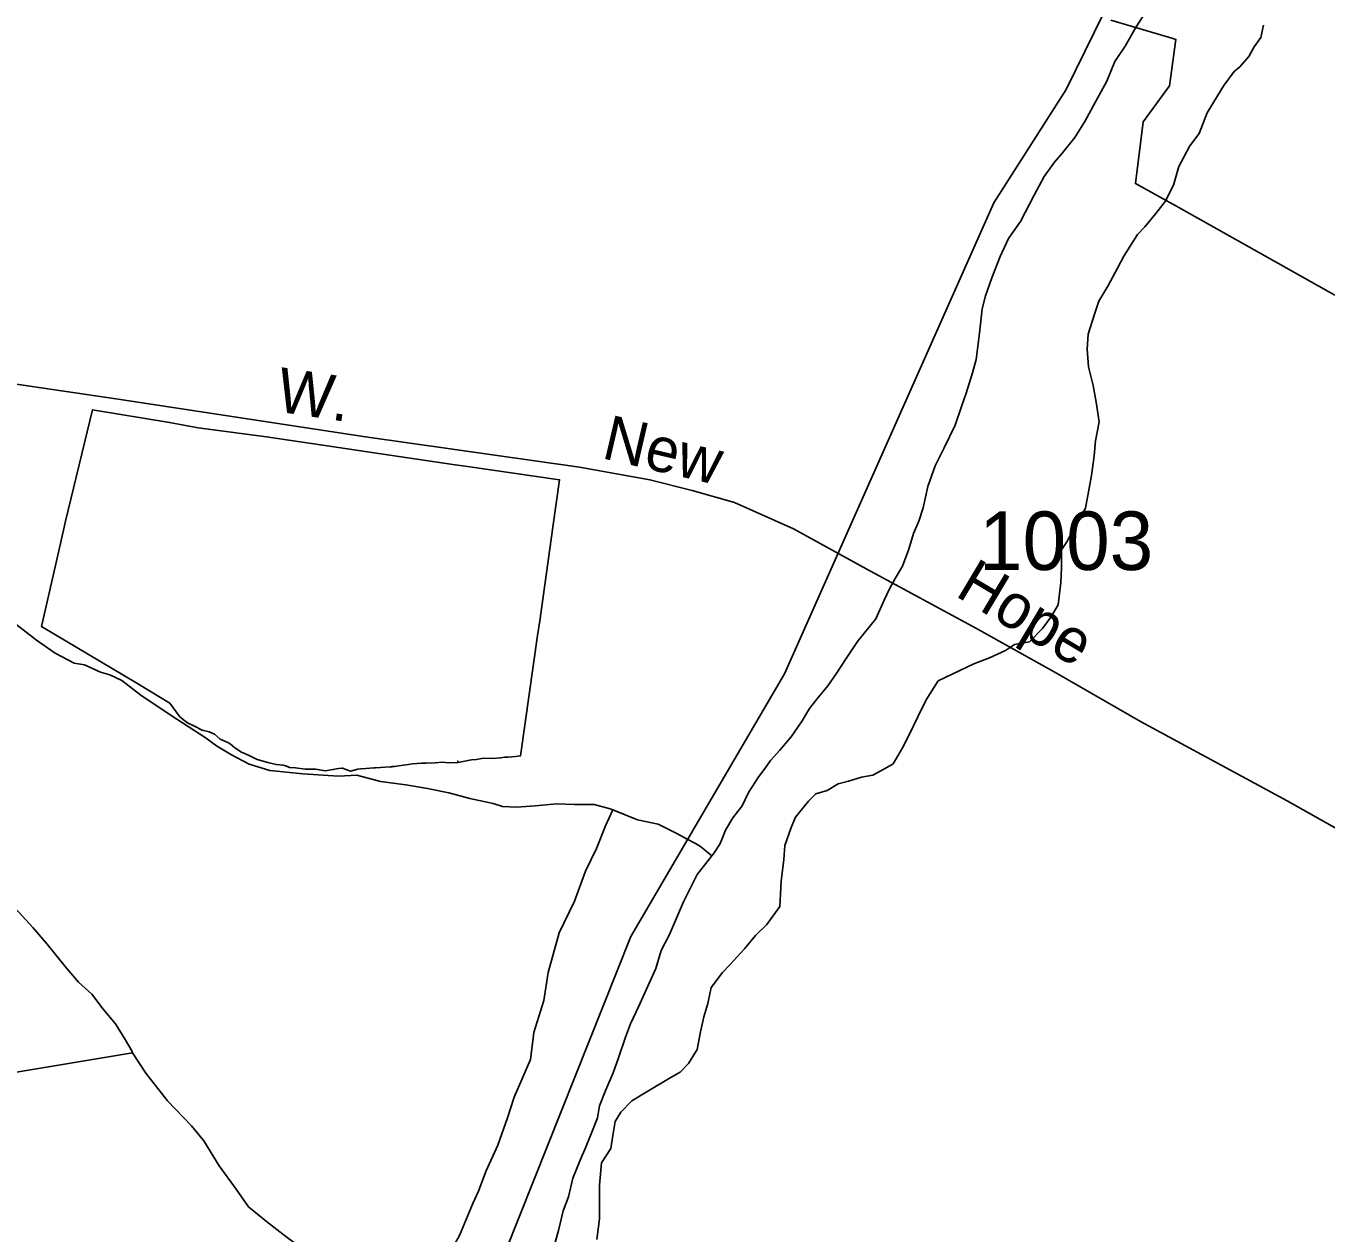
# Model space of a CAD drawing. Extents: x 2260773 to 2342389, y 552869 to 618546.
# Drawn here: x 2309662 to 2312438, y 605993 to 608571 of the extents above; entities that cross this region are included whole.
import ezdxf

# ---------------------------------------------------------------- set-up
doc = ezdxf.new("R2010")
doc.units = 0
for name, color, linetype in [('Exist Boundary Political City Limit New', 7, 'Continuous'), ('Exist Hydrographic Creek Single Shore', 7, 'Continuous'), ('Exist Hydrographic Misc Water Feature', 7, 'Continuous'), ('Exist Road Secondary Type 51 Attributed', 7, 'Continuous'), ('Exist Road Secondary Type 51 Label', 7, 'Continuous'), ('Exist Road Secondary Type 51 Number Label', 7, 'Continuous'), ('Map Preparation Boundary City Limit Buffer Line', 7, 'Continuous')]:
    doc.layers.add(name, color=color, linetype=linetype)

msp = doc.modelspace()

# ---------------------------------------------------------------- linework, layer by layer
at = {"layer": 'Exist Boundary Political City Limit New'}
for points in [[(2312456.5, 607995.6), (2312123.2, 608182.8), (2312030.8, 608234.4), (2312047.2, 608366.1), (2312103.8, 608442.9), (2312117.2, 608542.2), (2312108.8, 608544.8), (2311978.5, 608583.2)], [(2310419, 607657.1), (2310578, 607633.8), (2310583.5, 607633), (2310599.2, 607630.7), (2310801, 607601.7), (2310786.5, 607500), (2310758.5, 607299.9), (2310754, 607268.6), (2310718.5, 607016.7), (2310717.8, 607012.2), (2310707.2, 607010.8), (2310691, 607009.1), (2310683.5, 607008.8), (2310675.5, 607007.5), (2310657.8, 607006.5), (2310638.8, 607007.2), (2310623.5, 607004.1), (2310613.2, 607003), (2310605.5, 607002.2), (2310584.2, 606997.8), (2310583.5, 607001), (2310583.5, 606997.8), (2310563, 606996.6), (2310550.2, 606998.4), (2310535.2, 606997.2), (2310516, 606996.2), (2310505.8, 606995.9), (2310497.2, 606995.6), (2310486, 606994.6), (2310478.2, 606993.6), (2310457, 606990.5), (2310448.5, 606989.2), (2310445, 606988.9), (2310444.2, 606988.8), (2310443.2, 606988.7), (2310439.2, 606988.3), (2310418.8, 606986.7), (2310408.2, 606986.2), (2310404.2, 606986), (2310387.5, 606985), (2310376.2, 606983.9), (2310370, 606983.3), (2310354.5, 606978.8), (2310347, 606981.8), (2310337.2, 606985.8), (2310336.5, 606985.7), (2310335.8, 606985.6), (2310329.2, 606985.1), (2310317, 606982.4), (2310301, 606980.2), (2310279.5, 606983.4), (2310257.5, 606983.2), (2310237.2, 606986.2), (2310224.5, 606987.2), (2310216.2, 606990.3), (2310215.5, 606990.8), (2310210.5, 606991.7), (2310196, 606993.6), (2310177.8, 606997.6), (2310155.2, 607004.3), (2310138, 607012.4), (2310121.8, 607019.6), (2310107.8, 607028.8), (2310097.2, 607037.8), (2310092.8, 607040.2), (2310076, 607047.5), (2310063.8, 607058.2), (2310052.5, 607062.9), (2310037.5, 607066.9), (2310021, 607075.5), (2310006.5, 607082.1), (2310000.8, 607086.6), (2309990.2, 607095.1), (2309968.5, 607124.5), (2309898.5, 607166.9), (2309894.8, 607169.5), (2309720.8, 607272.5), (2309694.8, 607287.8), (2309731.5, 607449.9), (2309743, 607500), (2309746, 607512.8), (2309803.2, 607751), (2309968, 607723.9), (2310029, 607712.8), (2310175.2, 607693), (2310198.5, 607689.6), (2310295.2, 607675.3), (2310419, 607657.1)]]:
    msp.add_lwpolyline(points, dxfattribs=at)
at = {"layer": 'Exist Hydrographic Creek Single Shore'}
msp.add_lwpolyline([(2310686.2, 605955.4), (2310953.2, 606625.8), (2311281.1, 607187.1), (2311728.1, 608192.9), (2311883.1, 608435.5), (2312022.1, 608720)], dxfattribs=at)
at = {"layer": 'Exist Hydrographic Misc Water Feature'}
for points in [[(2312063.9, 608617.8), (2312032.6, 608569.4), (2312009, 608527.5), (2311987.1, 608495.1), (2311969.8, 608453), (2311945.8, 608408.8), (2311922.7, 608366.5), (2311901.3, 608332.4), (2311875.1, 608300.2), (2311857.7, 608279.7), (2311836.1, 608249.7), (2311814.6, 608209.2), (2311785.3, 608153.2), (2311759.6, 608116.9), (2311741.8, 608078.6), (2311724.4, 608032.6), (2311710.8, 607994.4), (2311703.1, 607966.4), (2311697.9, 607914.5), (2311690.3, 607858.4), (2311682.5, 607830), (2311669.2, 607786.2), (2311659.6, 607758), (2311646, 607717.9), (2311622.3, 607669.6), (2311602.8, 607631.6), (2311587.4, 607587.2), (2311577.6, 607541.3), (2311568.1, 607513.1), (2311556.6, 607486.8), (2311546.8, 607453), (2311533.1, 607417), (2311517.3, 607390.6), (2311505.4, 607368.4), (2311493.9, 607344.6), (2311476.5, 607304.2), (2311436.9, 607255.8), (2311413.1, 607219.7), (2311391.6, 607187.3), (2311373.9, 607161.1), (2311350.2, 607133), (2311334.6, 607112.7), (2311318.8, 607086.7), (2311295.2, 607052.5), (2311271.4, 607024.1), (2311251.5, 607001.9), (2311239.8, 606985.8), (2311226.3, 606967.6), (2311204.4, 606933.6), (2311190.8, 606905.2), (2311171.1, 606879.4), (2311155.4, 606853), (2311147.8, 606833), (2311143.5, 606823.1), (2311129.9, 606802.8), (2311125.8, 606798.6)], [(2310880.6, 605978.6), (2310886.3, 606022.8), (2310886.1, 606062.5), (2310885.9, 606094.6), (2310890.8, 606142.5), (2310910.7, 606172.8), (2310914.6, 606200.6), (2310920, 606231), (2310931.9, 606251.1), (2310955.4, 606275.1), (2310989.5, 606295.6), (2311037, 606324.1), (2311058.8, 606336.2), (2311076.6, 606354.6), (2311094.5, 606384.8), (2311102, 606422.6), (2311109.4, 606454.7), (2311117.4, 606482.7), (2311124.8, 606516.9), (2311148.6, 606549), (2311164.4, 606565.3), (2311196, 606599.8), (2311219.5, 606628), (2311243.3, 606651.9), (2311271, 606690.4), (2311274.1, 606744.2), (2311279.6, 606790.4), (2311281.7, 606820.6), (2311295.2, 606858.7), (2311304.8, 606880.7), (2311332.7, 606915.1), (2311348.5, 606930.9), (2311372.5, 606937.5), (2311396.1, 606951.8), (2311418, 606957.8), (2311445.7, 606966.2), (2311469.7, 606970.3), (2311499.6, 606986.8), (2311513.4, 606994.9), (2311533.1, 607028.9), (2311546.8, 607055.2), (2311566.3, 607095.2), (2311584.1, 607131.5), (2311609.6, 607171.9), (2311639.1, 607186.1), (2311685.4, 607208.7), (2311718.8, 607221.1), (2311753.1, 607237), (2311772.6, 607249.5), (2311804.6, 607255.6), (2311832.2, 607283.9), (2311849.9, 607308.4), (2311865.7, 607334.4), (2311871.2, 607382.3), (2311872.6, 607414.5), (2311872.6, 607452.2), (2311884.3, 607468.7), (2311901.7, 607502.6), (2311923.9, 607541), (2311936.8, 607610.8), (2311942.6, 607653), (2311945.6, 607685), (2311953.6, 607725.1), (2311947.1, 607767.1), (2311940.7, 607802.9), (2311930.5, 607843), (2311927.8, 607880.7), (2311929.6, 607912.8), (2311943, 607955), (2311952.4, 607983.2), (2311972.1, 608015.1), (2311992.2, 608053.5), (2312005.9, 608079.4), (2312035.2, 608125.7), (2312050.6, 608142), (2312074.4, 608170.1), (2312094.1, 608196.3), (2312112.1, 608230.5), (2312123.4, 608270.6), (2312147, 608314.8), (2312166.7, 608341.1), (2312184.1, 608385.1), (2312206, 608421.6), (2312219.6, 608443.9), (2312241.5, 608473.8), (2312253.4, 608483.8), (2312272.7, 608506), (2312284.6, 608526.1), (2312298.5, 608546.3), (2312304.3, 608572.6)], [(2309633.1, 607298.3), (2309683.9, 607259), (2309723.9, 607231.4), (2309764.1, 607210), (2309786.4, 607206.2), (2309820.5, 607190.6), (2309840.4, 607184.7), (2309866.4, 607173.1), (2309906.6, 607141.5), (2309971.2, 607098.1), (2310019.6, 607066.9), (2310043.8, 607051.1), (2310068, 607033.3), (2310100, 607013.8), (2310138.3, 606993.9), (2310182.4, 606980.4), (2310252.7, 606973.4), (2310328.8, 606968.1), (2310368.2, 606970.6), (2310418.6, 606957), (2310472.7, 606949.7), (2310518.7, 606942.3), (2310564.6, 606932.5), (2310609.1, 606921), (2310658.9, 606909.8), (2310678.8, 606904), (2310709.2, 606902.3), (2310749.2, 606904.8), (2310794.9, 606909.3), (2310832.8, 606907.6), (2310875.1, 606908.1), (2310908.7, 606898.6), (2310914.8, 606896.4)], [(2310914.8, 606896.4), (2310899.2, 606862.3), (2310879.8, 606814.1), (2310856.4, 606765.7), (2310833, 606701.5), (2310800, 606633.5), (2310776.6, 606549), (2310767.6, 606489.2), (2310745.9, 606421), (2310738.9, 606362.9), (2310703.8, 606282.6), (2310690.1, 606238.4), (2310669, 606180), (2310643.3, 606123.8), (2310628, 606081.9), (2310615.9, 606055.8), (2310587.2, 605987.5), (2310563.6, 605945.3), (2310538.2, 605904.9), (2310516.4, 605866.8), (2310506.6, 605832.6)], [(2310914.8, 606896.4), (2310967.3, 606875.2), (2311011.6, 606865.7), (2311031.3, 606855.8), (2311051.2, 606845.9), (2311071.9, 606834.3), (2311091.4, 606824.4), (2311101.6, 606818.5), (2311125.8, 606798.6)], [(2311125.8, 606798.6), (2311094.5, 606758.3), (2311065.3, 606700.3), (2311035.8, 606630.1), (2311018.2, 606595.8), (2311006.7, 606557.8), (2310992.8, 606527.5), (2310969.2, 606475.4), (2310952.2, 606439.1), (2310941.9, 606411), (2310926.5, 606367.1), (2310915.2, 606334.8), (2310899.5, 606298.6), (2310886.1, 606264.5), (2310882.2, 606238.3), (2310868.5, 606204.3), (2310856.6, 606174.5), (2310845.1, 606148.2), (2310829.3, 606110), (2310819.7, 606070.1), (2310808.4, 606039.8), (2310798.8, 605997.8), (2310785.2, 605949.6)], [(2309637.6, 606686.9), (2309676.1, 606645.4), (2309706.7, 606609.5), (2309745.2, 606562), (2309773.5, 606528.5), (2309802, 606502.7), (2309826, 606471.1), (2309852.3, 606439.2), (2309873, 606405.7), (2309887.3, 606381.6), (2309889.2, 606377.7)], [(2308874.4, 606316.8), (2308890.4, 606313.1), (2308930.3, 606313.6), (2308988.4, 606319.8), (2309079.8, 606331.2), (2309152.8, 606263.9), (2309202.4, 606268.6), (2309202.6, 606264.5), (2309402.2, 606296.5), (2309709.5, 606347.9), (2309889.2, 606377.7)], [(2309889.2, 606377.7), (2309917.7, 606334), (2309963.8, 606274.8), (2310014.9, 606221.3), (2310041.1, 606189.4), (2310073.7, 606135.8), (2310110, 606086.1), (2310136.7, 606048.5), (2310174.8, 606017.1), (2310219.3, 605983.3), (2310251.5, 605959.8), (2310273.6, 605950), (2310297.8, 605934.5), (2310333.9, 605918.6), (2310386, 605895.3), (2310421.9, 605883.8), (2310470.5, 605858.3), (2310506.6, 605832.6)]]:
    msp.add_lwpolyline(points, dxfattribs=at)
at = {"layer": 'Exist Road Secondary Type 51 Attributed'}
msp.add_lwpolyline([(2308224.8, 607981.7), (2308286.9, 607941.1), (2308405.3, 607888.6), (2308625.9, 607825), (2308713.7, 607811), (2308806.6, 607800.8), (2309323.5, 607821.2), (2309464.4, 607818.1), (2309523.4, 607816.8), (2309524.1, 607816.7), (2309626.5, 607807.8), (2309858.3, 607773.4), (2310386.6, 607693.2), (2310843.7, 607628.2), (2310993.9, 607601.5), (2311084.3, 607578.5), (2311174.7, 607553), (2311300.7, 607497), (2311457.3, 607410.4), (2311691.6, 607284.2), (2311862.2, 607188.7), (2312041.7, 607085.5), (2312354.9, 606916.1), (2312688.4, 606727.5)], dxfattribs=at)
at = {"layer": 'Map Preparation Boundary City Limit Buffer Line'}
for points in [[(2312456.5, 607995.6), (2312123.2, 608182.8), (2312030.8, 608234.4), (2312047.2, 608366.1), (2312103.8, 608442.9), (2312117.2, 608542.2), (2312108.8, 608544.8), (2311978.5, 608583.2)], [(2310419, 607657.1), (2310578, 607633.8), (2310583.5, 607633), (2310599.2, 607630.7), (2310801, 607601.7), (2310786.5, 607500), (2310758.5, 607299.9), (2310754, 607268.6), (2310718.5, 607016.7), (2310717.8, 607012.2), (2310707.2, 607010.8), (2310691, 607009.1), (2310683.5, 607008.8), (2310675.5, 607007.5), (2310657.8, 607006.5), (2310638.8, 607007.2), (2310623.5, 607004.1), (2310613.2, 607003), (2310605.5, 607002.2), (2310584.2, 606997.8), (2310583.5, 607001), (2310583.5, 606997.8), (2310563, 606996.6), (2310550.2, 606998.4), (2310535.2, 606997.2), (2310516, 606996.2), (2310505.8, 606995.9), (2310497.2, 606995.6), (2310486, 606994.6), (2310478.2, 606993.6), (2310457, 606990.5), (2310448.5, 606989.2), (2310445, 606988.9), (2310444.2, 606988.8), (2310443.2, 606988.7), (2310439.2, 606988.3), (2310418.8, 606986.7), (2310408.2, 606986.2), (2310404.2, 606986), (2310387.5, 606985), (2310376.2, 606983.9), (2310370, 606983.3), (2310354.5, 606978.8), (2310347, 606981.8), (2310337.2, 606985.8), (2310336.5, 606985.7), (2310335.8, 606985.6), (2310329.2, 606985.1), (2310317, 606982.4), (2310301, 606980.2), (2310279.5, 606983.4), (2310257.5, 606983.2), (2310237.2, 606986.2), (2310224.5, 606987.2), (2310216.2, 606990.3), (2310215.5, 606990.8), (2310210.5, 606991.7), (2310196, 606993.6), (2310177.8, 606997.6), (2310155.2, 607004.3), (2310138, 607012.4), (2310121.8, 607019.6), (2310107.8, 607028.8), (2310097.2, 607037.8), (2310092.8, 607040.2), (2310076, 607047.5), (2310063.8, 607058.2), (2310052.5, 607062.9), (2310037.5, 607066.9), (2310021, 607075.5), (2310006.5, 607082.1), (2310000.8, 607086.6), (2309990.2, 607095.1), (2309968.5, 607124.5), (2309898.5, 607166.9), (2309894.8, 607169.5), (2309720.8, 607272.5), (2309694.8, 607287.8), (2309731.5, 607449.9), (2309743, 607500), (2309746, 607512.8), (2309803.2, 607751), (2309968, 607723.9), (2310029, 607712.8), (2310175.2, 607693), (2310198.5, 607689.6), (2310295.2, 607675.3), (2310419, 607657.1)]]:
    msp.add_lwpolyline(points, dxfattribs=at)

# ---------------------------------------------------------------- texts
at = {"layer": 'Exist Road Secondary Type 51 Label'}
for s, rotation, p in [('W.', 351.5009, (2310193, 607748)), ('New', 346.825, (2310888.3, 607648.3)), ('Hope', 329.1995, (2311643.2, 607354.9))]:
    msp.add_text(s, height=95, rotation=rotation, dxfattribs=at).set_placement(p)
at = {"layer": 'Exist Road Secondary Type 51 Number Label'}
msp.add_text('1003', height=125, dxfattribs=at).set_placement((2311696.8, 607408.8))

doc.saveas('drawing.dxf')
